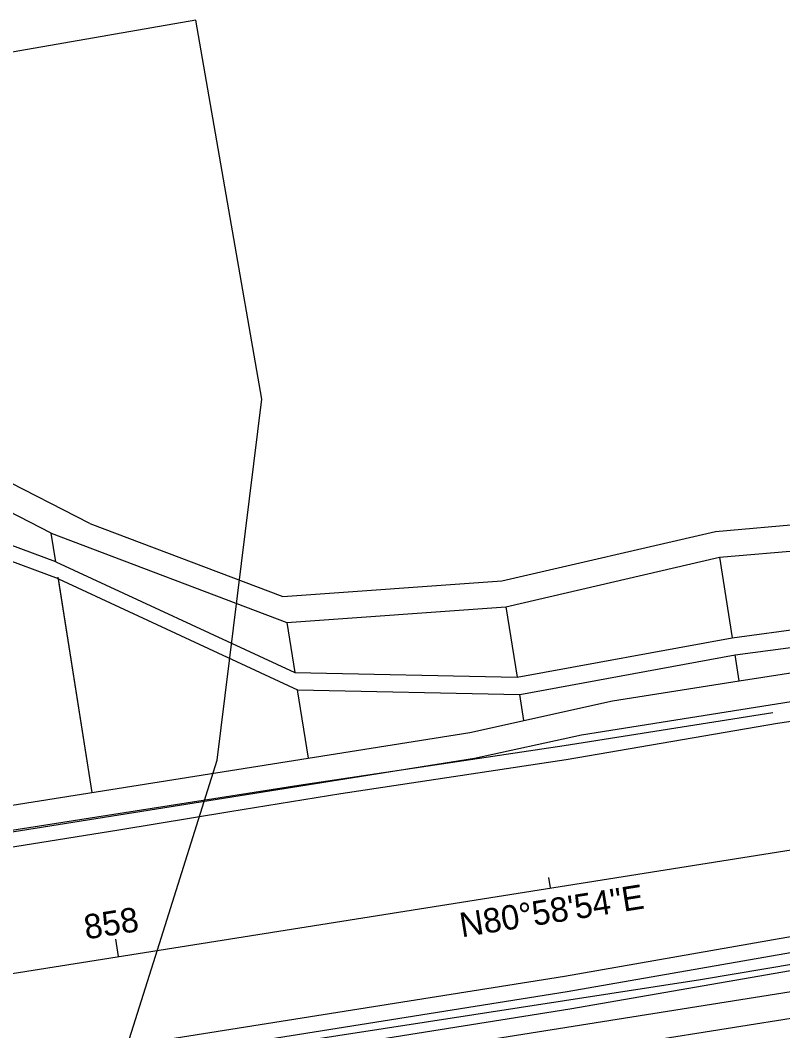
# Model space of a CAD drawing. Extents: x 115987 to 120394, y 324408 to 325987.
# Drawn here: x 117337.5 to 117424.6, y 325455.4 to 325571 of the extents above; entities that cross this region are included whole.
import ezdxf

# ---------------------------------------------------------------- set-up
doc = ezdxf.new("R2010")
doc.units = 0
for name, color, linetype in [('DR_X_Headwall', 7, 'Continuous'), ('DT_X_Break_Line', 7, 'Continuous'), ('DT_X_Contour_Major', 7, 'Continuous'), ('DT_X_Contour_Minor', 7, 'Continuous'), ('DT_X_Terrain_Boundary', 7, 'Continuous'), ('DT_X_Triangles', 7, 'Continuous'), ('PV_X_EOP', 7, 'Continuous'), ('PV_X_Shoulder', 7, 'Continuous'), ('RW_X_Esmt_LA', 7, 'Continuous'), ('RW_X_Text', 7, 'Continuous'), ('SC_Scratch1', 7, 'Continuous'), ('SV_X_Break_Lines', 7, 'Continuous'), ('UT_X_Gas_Cells', 7, 'Continuous')]:
    doc.layers.add(name, color=color, linetype=linetype)

msp = doc.modelspace()

# ---------------------------------------------------------------- linework, layer by layer
at = {"layer": 'DR_X_Headwall'}
msp.add_lwpolyline([(117357.55, 325570.98), (117273.82, 325556.38), (117277.6, 325534.71), (117281.38, 325513.03), (117278.93, 325511.93), (117272.32, 325490.95), (117265.71, 325469.96), (117259.1, 325448.98), (117252.5, 325428), (117245.89, 325407.01), (117239.28, 325386.03), (117232.67, 325365.04), (117313.74, 325339.51), (117320.35, 325360.49), (117326.96, 325381.48), (117333.57, 325402.46), (117340.18, 325423.45), (117346.79, 325444.43), (117353.4, 325465.41), (117360.01, 325486.4), (117365.11, 325527.64), (117361.33, 325549.31)], close=True, dxfattribs=at)
at = {"layer": 'DT_X_Break_Line'}
msp.add_lwpolyline([(117211.7, 325457.57), (117213.56, 325458.2), (117225.96, 325459.99), (117250.72, 325464.38), (117309.04, 325474.06), (117338.5, 325478.7), (117369.33, 325483.52), (117399.67, 325488.05), (117423.5, 325491.85)], dxfattribs=at)
at = {"layer": 'DT_X_Contour_Major'}
msp.add_line((117052.43, 325416.91), (117570.94, 325499.21), dxfattribs=at)
at = {"layer": 'DT_X_Contour_Minor'}
for p, q in [((117400.3, 325457.95), (117498.82, 325475.16)), ((117202.77, 325426.6), (117400.3, 325457.95))]:
    msp.add_line(p, q, dxfattribs=at)
at = {"layer": 'DT_X_Terrain_Boundary'}
for p, q in [((117398.1, 325471.77), (117397.91, 325472.96)), ((117348.72, 325463.94), (117348.41, 325465.91))]:
    msp.add_line(p, q, dxfattribs=at)
at = {"layer": 'DT_X_Triangles'}
for p, q in [((117399.7, 325461.7), (117498.22, 325478.91)), ((117399.98, 325459.92), (117498.5, 325477.13)), ((117202.17, 325430.35), (117399.7, 325461.7)), ((117202.45, 325428.57), (117399.98, 325459.92))]:
    msp.add_line(p, q, dxfattribs=at)
msp.add_lwpolyline([(117099.65, 325438.36), (117125.38, 325442.42), (117148.92, 325446.09), (117171.45, 325449.83), (117197.23, 325453.75), (117224.14, 325458.05), (117249.57, 325462.07), (117275.34, 325466.27), (117291.59, 325468.95), (117308.28, 325471.78), (117324.97, 325474.61), (117348.76, 325478.42), (117361.44, 325480.5), (117374.12, 325482.58), (117399.9, 325486.47), (117424.04, 325490.6), (117450.84, 325494.57), (117494.61, 325501.66)], dxfattribs=at)
at = {"layer": 'PV_X_EOP'}
for p, q in [((117341.04, 325512.34), (117329.69, 325518.15)), ((117341.56, 325509.07), (117341.04, 325512.34)), ((117341.04, 325512.34), (117367.97, 325502.12)), ((117417.41, 325509.58), (117442.38, 325511.76)), ((117393, 325503.92), (117417.41, 325509.58)), ((117417.41, 325509.58), (117418.87, 325500.38)), ((117345.74, 325482.7), (117341.84, 325507.29)), ((117345.74, 325482.7), (117341.87, 325507.1)), ((117367.97, 325502.12), (117393, 325503.92)), ((117393, 325503.92), (117394.28, 325495.87)), ((117367.97, 325502.12), (117368.88, 325496.4)), ((117419.66, 325495.45), (117444.35, 325499.36)), ((117419.66, 325495.45), (117419.19, 325498.41)), ((117370.43, 325486.62), (117369.19, 325494.42)), ((117405.17, 325493.15), (117419.66, 325495.45)), ((117395.06, 325490.92), (117394.59, 325493.9)), ((117388.86, 325489.55), (117405.17, 325493.15)), ((117253.24, 325468.02), (117388.86, 325489.55)), ((117234.5, 325426.57), (117468.89, 325463.77))]:
    msp.add_line(p, q, dxfattribs=at)
at = {"layer": 'PV_X_Shoulder'}
for p, q in [((117341.56, 325509.07), (117330.47, 325513.19)), ((117341.87, 325507.1), (117330.79, 325511.21)), ((117341.56, 325509.07), (117368.88, 325496.4)), ((117341.87, 325507.1), (117369.19, 325494.42)), ((117418.87, 325500.38), (117443.66, 325503.71)), ((117419.19, 325498.41), (117443.97, 325501.74)), ((117394.28, 325495.87), (117418.87, 325500.38)), ((117394.59, 325493.9), (117419.19, 325498.41)), ((117368.88, 325496.4), (117394.28, 325495.87)), ((117369.19, 325494.42), (117394.59, 325493.9))]:
    msp.add_line(p, q, dxfattribs=at)
at = {"layer": 'RW_X_Esmt_LA'}
msp.add_line((117233.95, 325429.52), (117468.51, 325466.75), dxfattribs=at)
at = {"layer": 'RW_X_Text'}
for p, q in [((117401.65, 325489.3), (117451.03, 325497.13)), ((117389.42, 325486.6), (117401.65, 325489.3)), ((117253.62, 325465.04), (117389.42, 325486.6))]:
    msp.add_line(p, q, dxfattribs=at)
at = {"layer": 'SV_X_Break_Lines'}
msp.add_lwpolyline([(117201.97, 325427.68), (117227.38, 325431.66), (117252.1, 325435.74), (117280.03, 325440.3), (117292.79, 325442.11), (117309.87, 325444.81), (117326.13, 325447.51), (117353.09, 325451.69), (117415.24, 325461.3), (117441.01, 325465.67), (117487.67, 325473.31)], dxfattribs=at)
at = {"layer": 'UT_X_Gas_Cells'}
for p, q in [((117345.46, 325513.45), (117331.85, 325520.42)), ((117416.94, 325512.54), (117441.91, 325514.73)), ((117345.46, 325513.45), (117367.5, 325505.08)), ((117392.53, 325506.89), (117416.94, 325512.54)), ((117367.5, 325505.08), (117392.53, 325506.89))]:
    msp.add_line(p, q, dxfattribs=at)

# ---------------------------------------------------------------- texts
at = {"layer": 'DT_X_Terrain_Boundary'}
msp.add_text('858', height=2.8, rotation=9.0184, dxfattribs=at).set_placement((117345.03, 325465.88))
at = {"layer": 'SC_Scratch1'}
msp.add_text('N80°58\'54"E', height=2.8, rotation=9.0184, dxfattribs=at).set_placement((117387.95, 325466.12))

doc.saveas('drawing.dxf')
